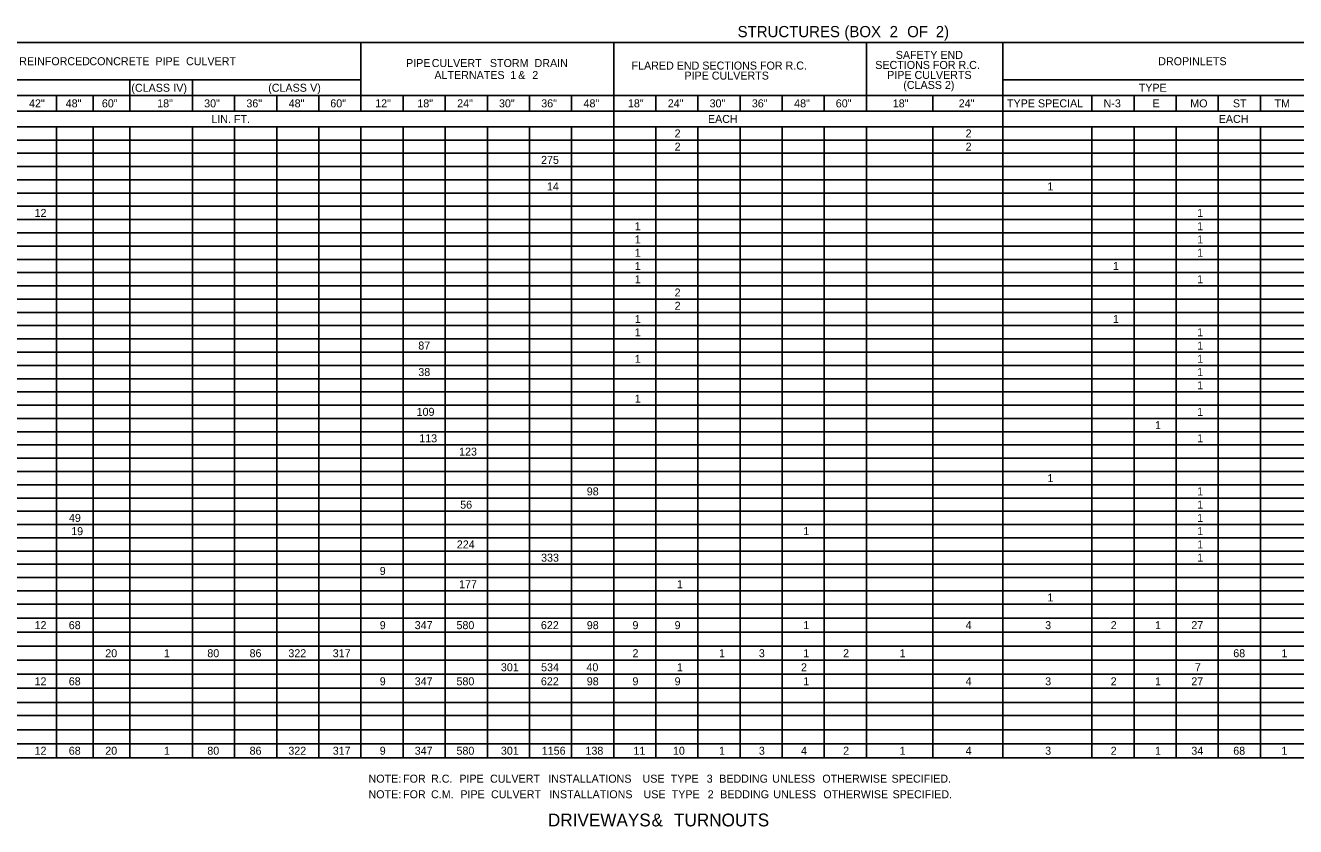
# Model space of a CAD drawing. Extents: x 1226561 to 1228164, y 151309 to 152305.
# Drawn here: x 1226933 to 1227627, y 151837 to 152275 of the extents above; entities that cross this region are included whole.
import ezdxf

# ---------------------------------------------------------------- set-up
doc = ezdxf.new("R2010")
doc.units = 0
doc.layers.add('R_Dimension', color=7, linetype='Continuous')

msp = doc.modelspace()

# ---------------------------------------------------------------- linework, layer by layer
at = {"layer": 'R_Dimension'}
for p, q in [((1226564.67, 152265.3), (1228152.39, 152265.3)), ((1227116.78, 152227.8), (1227116.78, 152265.3)), ((1227254.86, 151874.5), (1227254.86, 152265.3)), ((1227392.94, 152227.8), (1227392.94, 152265.3)), ((1227467.53, 151874.5), (1227467.53, 152265.3)), ((1226850.27, 152244.85), (1227116.78, 152244.85)), ((1226990.48, 152227.8), (1226990.48, 152244.85)), ((1227024.73, 152227.8), (1227024.73, 152244.85)), ((1227467.53, 152244.85), (1227677.21, 152244.85)), ((1226850.27, 152236.32), (1227335.26, 152236.32)), ((1226950.42, 152227.8), (1226950.42, 152236.32)), ((1226970.45, 152227.8), (1226970.45, 152236.32)), ((1227047.74, 152227.8), (1227047.74, 152236.32)), ((1227070.75, 152227.8), (1227070.75, 152236.32)), ((1227093.77, 152227.8), (1227093.77, 152236.32)), ((1227139.79, 152227.8), (1227139.79, 152236.32)), ((1227162.81, 152227.8), (1227162.81, 152236.32)), ((1227185.82, 152227.8), (1227185.82, 152236.32)), ((1227208.83, 152227.8), (1227208.83, 152236.32)), ((1227231.85, 152227.8), (1227231.85, 152236.32)), ((1227277.88, 152227.8), (1227277.88, 152236.32)), ((1227300.89, 152227.8), (1227300.89, 152236.32)), ((1227312.25, 152236.32), (1228152.39, 152236.32)), ((1227323.9, 152227.8), (1227323.9, 152236.32)), ((1227346.92, 152227.8), (1227346.92, 152236.32)), ((1227369.93, 152227.8), (1227369.93, 152236.32)), ((1227429.17, 152227.8), (1227429.17, 152236.32)), ((1227516.11, 152227.8), (1227516.11, 152236.32)), ((1227539.12, 152227.8), (1227539.12, 152236.32)), ((1227562.14, 152227.8), (1227562.14, 152236.32)), ((1227585.15, 152227.8), (1227585.15, 152236.32)), ((1227608.16, 152227.8), (1227608.16, 152236.32)), ((1226850.27, 152227.8), (1228152.39, 152227.8)), ((1227467.53, 152227.8), (1228045.42, 152227.8)), ((1226564.67, 152219.27), (1228152.39, 152219.27)), ((1226950.42, 151874.5), (1226950.42, 152219.27)), ((1226970.45, 151874.5), (1226970.45, 152219.27)), ((1226990.48, 151874.5), (1226990.48, 152219.27)), ((1227024.73, 151874.5), (1227024.73, 152219.27)), ((1227047.74, 151874.5), (1227047.74, 152219.27)), ((1227070.75, 151874.5), (1227070.75, 152219.27)), ((1227093.77, 151874.5), (1227093.77, 152219.27)), ((1227116.78, 151874.5), (1227116.78, 152219.27)), ((1227139.79, 151874.5), (1227139.79, 152219.27)), ((1227162.81, 151874.5), (1227162.81, 152219.27)), ((1227185.82, 151874.5), (1227185.82, 152219.27)), ((1227208.83, 151874.5), (1227208.83, 152219.27)), ((1227231.85, 151874.5), (1227231.85, 152219.27)), ((1227277.88, 151874.5), (1227277.88, 152219.27)), ((1227300.89, 151874.5), (1227300.89, 152219.27)), ((1227323.9, 151874.5), (1227323.9, 152219.27)), ((1227346.92, 151874.5), (1227346.92, 152219.27)), ((1227369.93, 151874.5), (1227369.93, 152219.27)), ((1227392.94, 151874.5), (1227392.94, 152219.27)), ((1227429.17, 151874.5), (1227429.17, 152219.27)), ((1227516.11, 151874.5), (1227516.11, 152219.27)), ((1227539.12, 151874.5), (1227539.12, 152219.27)), ((1227562.14, 151874.5), (1227562.14, 152219.27)), ((1227585.15, 151874.5), (1227585.15, 152219.27)), ((1227608.16, 151874.5), (1227608.16, 152219.27)), ((1226564.67, 152212.03), (1228152.39, 152212.03)), ((1226564.67, 152204.78), (1228152.39, 152204.78)), ((1226564.67, 152197.54), (1228152.39, 152197.54)), ((1226564.67, 152190.29), (1228152.39, 152190.29)), ((1226564.67, 152183.05), (1228152.39, 152183.05)), ((1226564.67, 152175.8), (1228152.39, 152175.8)), ((1226564.67, 152168.56), (1228152.39, 152168.56)), ((1226564.67, 152161.31), (1228152.39, 152161.31)), ((1226564.67, 152154.07), (1228152.39, 152154.07)), ((1226564.67, 152146.82), (1228152.39, 152146.82)), ((1226564.67, 152139.58), (1228152.39, 152139.58)), ((1226564.67, 152132.33), (1228152.39, 152132.33)), ((1226564.67, 152125.09), (1228152.39, 152125.09)), ((1226564.67, 152117.84), (1228152.39, 152117.84)), ((1226564.67, 152110.6), (1228152.39, 152110.6)), ((1226564.67, 152103.35), (1228152.39, 152103.35)), ((1226564.67, 152096.11), (1228152.39, 152096.11)), ((1226564.67, 152088.86), (1228152.39, 152088.86)), ((1226564.67, 152081.62), (1228152.39, 152081.62)), ((1226564.67, 152074.37), (1228152.39, 152074.37)), ((1226564.67, 152067.13), (1228152.39, 152067.13)), ((1226564.67, 152059.88), (1228152.39, 152059.88)), ((1226564.67, 152052.64), (1228152.39, 152052.64)), ((1226564.67, 152045.39), (1228152.39, 152045.39)), ((1226564.67, 152038.15), (1228152.39, 152038.15)), ((1226564.67, 152030.9), (1228152.39, 152030.9)), ((1226564.67, 152023.66), (1228152.39, 152023.66)), ((1226564.67, 152016.41), (1228152.39, 152016.41)), ((1226564.67, 152009.17), (1228152.39, 152009.17)), ((1226564.67, 152001.92), (1228152.39, 152001.92)), ((1226564.67, 151994.68), (1228152.39, 151994.68)), ((1226564.67, 151987.43), (1228152.39, 151987.43)), ((1226564.67, 151980.19), (1228152.39, 151980.19)), ((1226564.67, 151972.94), (1228152.39, 151972.94)), ((1226564.67, 151965.7), (1228152.39, 151965.7)), ((1226564.67, 151958.45), (1228152.39, 151958.45)), ((1226564.67, 151950.78), (1228152.39, 151950.78)), ((1226564.67, 151943.11), (1228152.39, 151943.11)), ((1226564.67, 151935.44), (1228152.39, 151935.44)), ((1226950.42, 151912.43), (1226950.42, 151935.44)), ((1226970.45, 151912.43), (1226970.45, 151935.44)), ((1226990.48, 151912.43), (1226990.48, 151935.44)), ((1227024.73, 151912.43), (1227024.73, 151935.44)), ((1227047.74, 151912.43), (1227047.74, 151935.44)), ((1227070.75, 151912.43), (1227070.75, 151935.44)), ((1227093.77, 151912.43), (1227093.77, 151935.44)), ((1227116.78, 151912.43), (1227116.78, 151935.44)), ((1227116.78, 151912.43), (1227116.78, 151935.44)), ((1227139.79, 151912.43), (1227139.79, 151935.44)), ((1227162.81, 151912.43), (1227162.81, 151935.44)), ((1227185.82, 151912.43), (1227185.82, 151935.44)), ((1227208.83, 151912.43), (1227208.83, 151935.44)), ((1227231.85, 151912.43), (1227231.85, 151935.44)), ((1227254.86, 151912.43), (1227254.86, 151935.44)), ((1227254.86, 151912.43), (1227254.86, 151935.44)), ((1227277.88, 151912.43), (1227277.88, 151935.44)), ((1227300.89, 151912.43), (1227300.89, 151935.44)), ((1227323.9, 151912.43), (1227323.9, 151935.44)), ((1227346.92, 151912.43), (1227346.92, 151935.44)), ((1227369.93, 151912.43), (1227369.93, 151935.44)), ((1227392.94, 151912.43), (1227392.94, 151935.44)), ((1227392.94, 151912.43), (1227392.94, 151935.44)), ((1227429.17, 151912.43), (1227429.17, 151935.44)), ((1227467.53, 151912.43), (1227467.53, 151935.44)), ((1227467.53, 151912.43), (1227467.53, 151935.44)), ((1227516.11, 151912.43), (1227516.11, 151935.44)), ((1227539.12, 151912.43), (1227539.12, 151935.44)), ((1227562.14, 151912.43), (1227562.14, 151935.44)), ((1227585.15, 151912.43), (1227585.15, 151935.44)), ((1227608.16, 151912.43), (1227608.16, 151935.44)), ((1226564.67, 151927.77), (1228152.39, 151927.77)), ((1226564.67, 151920.1), (1228152.39, 151920.1)), ((1226564.67, 151912.43), (1228152.39, 151912.43)), ((1226564.67, 151904.75), (1228152.39, 151904.75)), ((1226950.42, 151874.5), (1226950.42, 151904.75)), ((1226970.45, 151874.5), (1226970.45, 151904.75)), ((1226990.48, 151874.5), (1226990.48, 151904.75)), ((1227024.73, 151874.5), (1227024.73, 151904.75)), ((1227047.74, 151874.5), (1227047.74, 151904.75)), ((1227070.75, 151874.5), (1227070.75, 151904.75)), ((1227093.77, 151874.5), (1227093.77, 151904.75)), ((1227116.78, 151874.5), (1227116.78, 151904.75)), ((1227116.78, 151874.5), (1227116.78, 151904.75)), ((1227139.79, 151874.5), (1227139.79, 151904.75)), ((1227162.81, 151874.5), (1227162.81, 151904.75)), ((1227185.82, 151874.5), (1227185.82, 151904.75)), ((1227208.83, 151874.5), (1227208.83, 151904.75)), ((1227231.85, 151874.5), (1227231.85, 151904.75)), ((1227254.86, 151874.5), (1227254.86, 151904.75)), ((1227254.86, 151874.5), (1227254.86, 151904.75)), ((1227277.88, 151874.5), (1227277.88, 151904.75)), ((1227300.89, 151874.5), (1227300.89, 151904.75)), ((1227323.9, 151874.5), (1227323.9, 151904.75)), ((1227346.92, 151874.5), (1227346.92, 151904.75)), ((1227369.93, 151874.5), (1227369.93, 151904.75)), ((1227392.94, 151874.5), (1227392.94, 151904.75)), ((1227392.94, 151874.5), (1227392.94, 151904.75)), ((1227429.17, 151874.5), (1227429.17, 151904.75)), ((1227467.53, 151874.5), (1227467.53, 151904.75)), ((1227467.53, 151874.5), (1227467.53, 151904.75)), ((1227516.11, 151874.5), (1227516.11, 151904.75)), ((1227539.12, 151874.5), (1227539.12, 151904.75)), ((1227562.14, 151874.5), (1227562.14, 151904.75)), ((1227585.15, 151874.5), (1227585.15, 151904.75)), ((1227608.16, 151874.5), (1227608.16, 151904.75)), ((1226564.67, 151897.51), (1228152.39, 151897.51)), ((1226564.67, 151889.84), (1228152.39, 151889.84)), ((1226564.67, 151882.17), (1228152.39, 151882.17)), ((1226564.67, 151874.5), (1228152.39, 151874.5))]:
    msp.add_line(p, q, dxfattribs=at)

# ---------------------------------------------------------------- texts
for s, height, p in [('STRUCTURES', 6.119, (1227322.54, 152268.21)), (' (BOX', 6.119, (1227378.62, 152268.21)), (' 2', 6.119, (1227403.34, 152268.21)), (' OF', 6.119, (1227412.93, 152268.21)), (' 2)', 6.119, (1227428.54, 152268.21)), ('REINFORCED', 4.371, (1226930.07, 152252.89)), (' CONCRETE', 4.371, (1226966.79, 152252.89)), (' PIPE', 4.371, (1227002.83, 152252.89)), (' CULVERT', 4.371, (1227019.59, 152252.89)), ('PIPE', 4.371, (1227141.41, 152251.9)), (' CULVERT', 4.371, (1227153.8, 152251.9)), (' STORM', 4.371, (1227185.6, 152251.9)), (' DRAIN', 4.371, (1227210, 152251.9)), ('SAFETY END ', 4.3711, (1227408.97, 152256.35)), ('DROP', 4.371, (1227552.37, 152252.89)), (' INLETS', 4.371, (1227567.62, 152252.89)), ('ALTERNATES', 4.371, (1227156.9, 152245.35)), (' 1', 4.371, (1227196.69, 152245.35)), (' &', 4.371, (1227201.06, 152245.35)), (' 2', 4.371, (1227208.73, 152245.35)), ('FLARED END SECTIONS FOR R.C.', 4.3711, (1227264.62, 152250.52)), ('PIPE CULVERTS', 4.3711, (1227293.5, 152245.04)), ('SECTIONS FOR R.C. ', 4.3711, (1227397.76, 152250.87)), ('PIPE CULVERTS ', 4.3711, (1227404.27, 152245.4)), ('(CLASS', 4.371, (1226991.34, 152238.4)), (' IV)', 4.371, (1227012.61, 152238.4)), ('(CLASS', 4.371, (1227066.11, 152238.4)), (' V)', 4.371, (1227087.38, 152238.4)), ('(CLASS 2)', 4.371, (1227413.08, 152239.93)), ('TYPE', 4.371, (1227541.71, 152238.4)), ('42"', 4.371, (1226935.43, 152229.87)), ('48"', 4.371, (1226955.46, 152229.87)), ('60"', 4.371, (1226975.22, 152229.87)), ('18"', 4.371, (1227005.44, 152229.87)), ('30"', 4.371, (1227031.09, 152229.87)), ('36"', 4.371, (1227054.17, 152229.87)), ('48"', 4.371, (1227077.29, 152229.87)), ('60"', 4.371, (1227100.02, 152229.87)), ('12"', 4.371, (1227124.55, 152229.87)), ('18"', 4.371, (1227147.57, 152229.87)), ('24"', 4.371, (1227169.34, 152229.87)), ('30"', 4.371, (1227192.18, 152229.87)), ('36"', 4.371, (1227215.27, 152229.87)), ('48"', 4.371, (1227238.38, 152229.87)), ('18"', 4.371, (1227262.63, 152229.87)), ('24"', 4.371, (1227284.41, 152229.87)), ('30"', 4.371, (1227307.25, 152229.87)), ('36"', 4.371, (1227330.33, 152229.87)), ('48"', 4.371, (1227353.45, 152229.87)), ('60"', 4.371, (1227376.19, 152229.87)), ('18"', 4.371, (1227407.32, 152229.87)), ('24"', 4.371, (1227443.37, 152229.87)), ('TYPE', 4.371, (1227469.74, 152229.87)), (' SPECIAL', 4.371, (1227485.02, 152229.87)), ('N-3', 4.371, (1227522.52, 152229.87)), ('E', 4.37, (1227549.29, 152229.87)), ('MO', 4.371, (1227569.87, 152229.87)), ('ST', 4.371, (1227593.16, 152229.87)), ('TM', 4.371, (1227615.92, 152229.87)), ('LIN. FT.', 4.371, (1227035.02, 152221.29)), ('EACH', 4.371, (1227306.35, 152221.35)), ('EACH', 4.371, (1227585.42, 152221.35)), ('2', 4.37, (1227288.14, 152213.47)), ('2', 4.37, (1227447.11, 152213.47)), ('2', 4.37, (1227288.14, 152206.22)), ('2', 4.37, (1227447.11, 152206.22)), ('275', 4.371, (1227215.18, 152198.98)), ('14', 4.371, (1227218.38, 152184.49)), ('1', 4.37, (1227491.82, 152184.49)), ('12', 4.371, (1226938.45, 152170)), ('1', 4.37, (1227573.64, 152170)), ('1', 4.37, (1227266.37, 152162.75)), ('1', 4.37, (1227573.64, 152162.75)), ('1', 4.37, (1227266.37, 152155.51)), ('1', 4.37, (1227573.64, 152155.51)), ('1', 4.37, (1227266.37, 152148.26)), ('1', 4.37, (1227573.64, 152148.26)), ('1', 4.37, (1227266.37, 152141.02)), ('1', 4.37, (1227527.62, 152141.02)), ('1', 4.37, (1227266.37, 152133.77)), ('1', 4.37, (1227573.64, 152133.77)), ('2', 4.37, (1227288.14, 152126.53)), ('2', 4.37, (1227288.14, 152119.28)), ('1', 4.37, (1227266.37, 152112.04)), ('1', 4.37, (1227527.62, 152112.04)), ('1', 4.37, (1227266.37, 152104.79)), ('1', 4.37, (1227573.64, 152104.79)), ('87', 4.371, (1227148.1, 152097.55)), ('1', 4.37, (1227573.64, 152097.55)), ('1', 4.37, (1227266.37, 152090.3)), ('1', 4.37, (1227573.64, 152090.3)), ('38', 4.371, (1227148.1, 152083.06)), ('1', 4.37, (1227573.64, 152083.06)), ('1', 4.37, (1227573.64, 152075.81)), ('1', 4.37, (1227266.37, 152068.57)), ('109', 4.371, (1227147.19, 152061.32)), ('1', 4.37, (1227573.64, 152061.32)), ('1', 4.37, (1227550.63, 152054.08)), ('113', 4.371, (1227148.62, 152046.83)), ('1', 4.37, (1227573.64, 152046.83)), ('123', 4.371, (1227170.39, 152039.59)), ('1', 4.37, (1227491.82, 152025.1)), ('98', 4.371, (1227240.15, 152017.85)), ('1', 4.37, (1227573.64, 152017.85)), ('56', 4.371, (1227170.99, 152010.61)), ('1', 4.37, (1227573.64, 152010.61)), ('49', 4.371, (1226957.22, 152003.36)), ('1', 4.37, (1227573.64, 152003.36)), ('19', 4.371, (1226958.46, 151996.12)), ('1', 4.37, (1227358.42, 151996.12)), ('1', 4.37, (1227573.64, 151996.12)), ('224', 4.371, (1227169.15, 151988.87)), ('1', 4.37, (1227573.64, 151988.87)), ('333', 4.371, (1227215.18, 151981.63)), ('1', 4.37, (1227573.64, 151981.63)), ('9', 4.37, (1227127.03, 151974.38)), ('177', 4.371, (1227170.39, 151967.14)), ('1', 4.37, (1227289.38, 151967.14)), ('1', 4.37, (1227491.82, 151959.89)), ('12', 4.371, (1226938.45, 151944.76)), ('68', 4.371, (1226957.13, 151944.76)), ('9', 4.37, (1227127.03, 151944.76)), ('347', 4.371, (1227146.14, 151944.76)), ('580', 4.371, (1227168.96, 151944.76)), ('622', 4.371, (1227215.08, 151944.76)), ('98', 4.371, (1227240.15, 151944.76)), ('9', 4.37, (1227265.11, 151944.76)), ('9', 4.37, (1227288.13, 151944.76)), ('1', 4.37, (1227358.42, 151944.76)), ('4', 4.37, (1227447.11, 151944.76)), ('3', 4.37, (1227490.58, 151944.76)), ('2', 4.37, (1227526.38, 151944.76)), ('1', 4.37, (1227550.63, 151944.76)), ('27', 4.371, (1227570.44, 151944.76)), ('20', 4.371, (1226977.08, 151929.42)), ('1', 4.37, (1227009.17, 151929.42)), ('80', 4.371, (1227032.84, 151929.42)), ('86', 4.371, (1227055.92, 151929.42)), ('322', 4.371, (1227077.1, 151929.42)), ('317', 4.371, (1227101.35, 151929.42)), ('2', 4.37, (1227265.13, 151929.42)), ('1', 4.37, (1227312.4, 151929.42)), ('3', 4.37, (1227334.17, 151929.42)), ('1', 4.37, (1227358.42, 151929.42)), ('2', 4.37, (1227380.2, 151929.42)), ('1', 4.37, (1227411.06, 151929.42)), ('68', 4.371, (1227593.35, 151929.42)), ('1', 4.37, (1227619.67, 151929.42)), ('301', 4.371, (1227193.23, 151921.75)), ('534', 4.371, (1227215.18, 151921.75)), ('40', 4.371, (1227239.97, 151921.75)), ('1', 4.37, (1227289.38, 151921.75)), ('2', 4.37, (1227357.18, 151921.75)), ('7', 4.37, (1227572.4, 151921.75)), ('12', 4.371, (1226938.45, 151914.08)), ('68', 4.371, (1226957.13, 151914.08)), ('9', 4.37, (1227127.03, 151914.08)), ('347', 4.371, (1227146.14, 151914.08)), ('580', 4.371, (1227168.96, 151914.08)), ('622', 4.371, (1227215.08, 151914.08)), ('98', 4.371, (1227240.15, 151914.08)), ('9', 4.37, (1227265.11, 151914.08)), ('9', 4.37, (1227288.13, 151914.08)), ('1', 4.37, (1227358.42, 151914.08)), ('4', 4.37, (1227447.11, 151914.08)), ('3', 4.37, (1227490.58, 151914.08)), ('2', 4.37, (1227526.38, 151914.08)), ('1', 4.37, (1227550.63, 151914.08)), ('27', 4.371, (1227570.44, 151914.08)), ('12', 4.371, (1226938.45, 151876.15)), ('68', 4.371, (1226957.13, 151876.15)), ('20', 4.371, (1226977.08, 151876.15)), ('1', 4.37, (1227009.17, 151876.15)), ('80', 4.371, (1227032.84, 151876.15)), ('86', 4.371, (1227055.92, 151876.15)), ('322', 4.371, (1227077.1, 151876.15)), ('317', 4.371, (1227101.35, 151876.15)), ('9', 4.37, (1227127.03, 151876.15)), ('347', 4.371, (1227146.14, 151876.15)), ('580', 4.371, (1227168.96, 151876.15)), ('301', 4.371, (1227193.23, 151876.15)), ('1156', 4.371, (1227215.57, 151876.15)), ('138', 4.371, (1227239.43, 151876.15)), ('11', 4.371, (1227265.65, 151876.15)), ('10', 4.371, (1227287.23, 151876.15)), ('1', 4.37, (1227312.4, 151876.15)), ('3', 4.37, (1227334.17, 151876.15)), ('4', 4.37, (1227357.18, 151876.15)), ('2', 4.37, (1227380.2, 151876.15)), ('1', 4.37, (1227411.06, 151876.15)), ('4', 4.37, (1227447.11, 151876.15)), ('3', 4.37, (1227490.58, 151876.15)), ('2', 4.37, (1227526.38, 151876.15)), ('1', 4.37, (1227550.63, 151876.15)), ('34', 4.371, (1227570.44, 151876.15)), ('68', 4.371, (1227593.35, 151876.15)), ('1', 4.37, (1227619.67, 151876.15)), ('NOTE:', 4.371, (1227120.89, 151860.88)), (' FOR', 4.371, (1227138.17, 151860.88)), (' R.C.', 4.371, (1227153.45, 151860.88)), (' PIPE', 4.371, (1227168.91, 151860.88)), (' CULVERT', 4.371, (1227185.67, 151860.88)), (' INSTALLATIONS', 4.3711, (1227217.47, 151860.88)), (' USE', 4.371, (1227268.99, 151860.88)), (' TYPE', 4.371, (1227284.38, 151860.88)), (' 3', 4.371, (1227304.03, 151860.88)), (' BEDDING', 4.371, (1227310.88, 151860.88)), (' UNLESS', 4.371, (1227339.86, 151860.88)), (' OTHERWISE', 4.371, (1227367.22, 151860.88)), (' SPECIFIED.', 4.3711, (1227405.05, 151860.88)), ('NOTE:', 4.371, (1227120.89, 151852.36)), (' FOR', 4.371, (1227138.17, 151852.36)), (' C.M.', 4.371, (1227153.45, 151852.36)), (' PIPE', 4.371, (1227169.46, 151852.36)), (' CULVERT', 4.371, (1227186.22, 151852.36)), (' INSTALLATIONS', 4.3711, (1227218.02, 151852.36)), (' USE', 4.371, (1227269.54, 151852.36)), (' TYPE', 4.371, (1227284.93, 151852.36)), (' 2', 4.371, (1227304.58, 151852.36)), (' BEDDING', 4.371, (1227311.43, 151852.36)), (' UNLESS', 4.371, (1227340.41, 151852.36)), (' OTHERWISE', 4.371, (1227367.77, 151852.36)), (' SPECIFIED.', 4.3711, (1227405.6, 151852.36)), ('DRIVEWAYS', 7, (1227218.91, 151836.98)), (' &', 7, (1227272.92, 151836.98)), (' TURNOUTS', 7, (1227285.21, 151836.98))]:
    msp.add_text(s, height=height, dxfattribs=at).set_placement(p)

doc.saveas('drawing.dxf')
